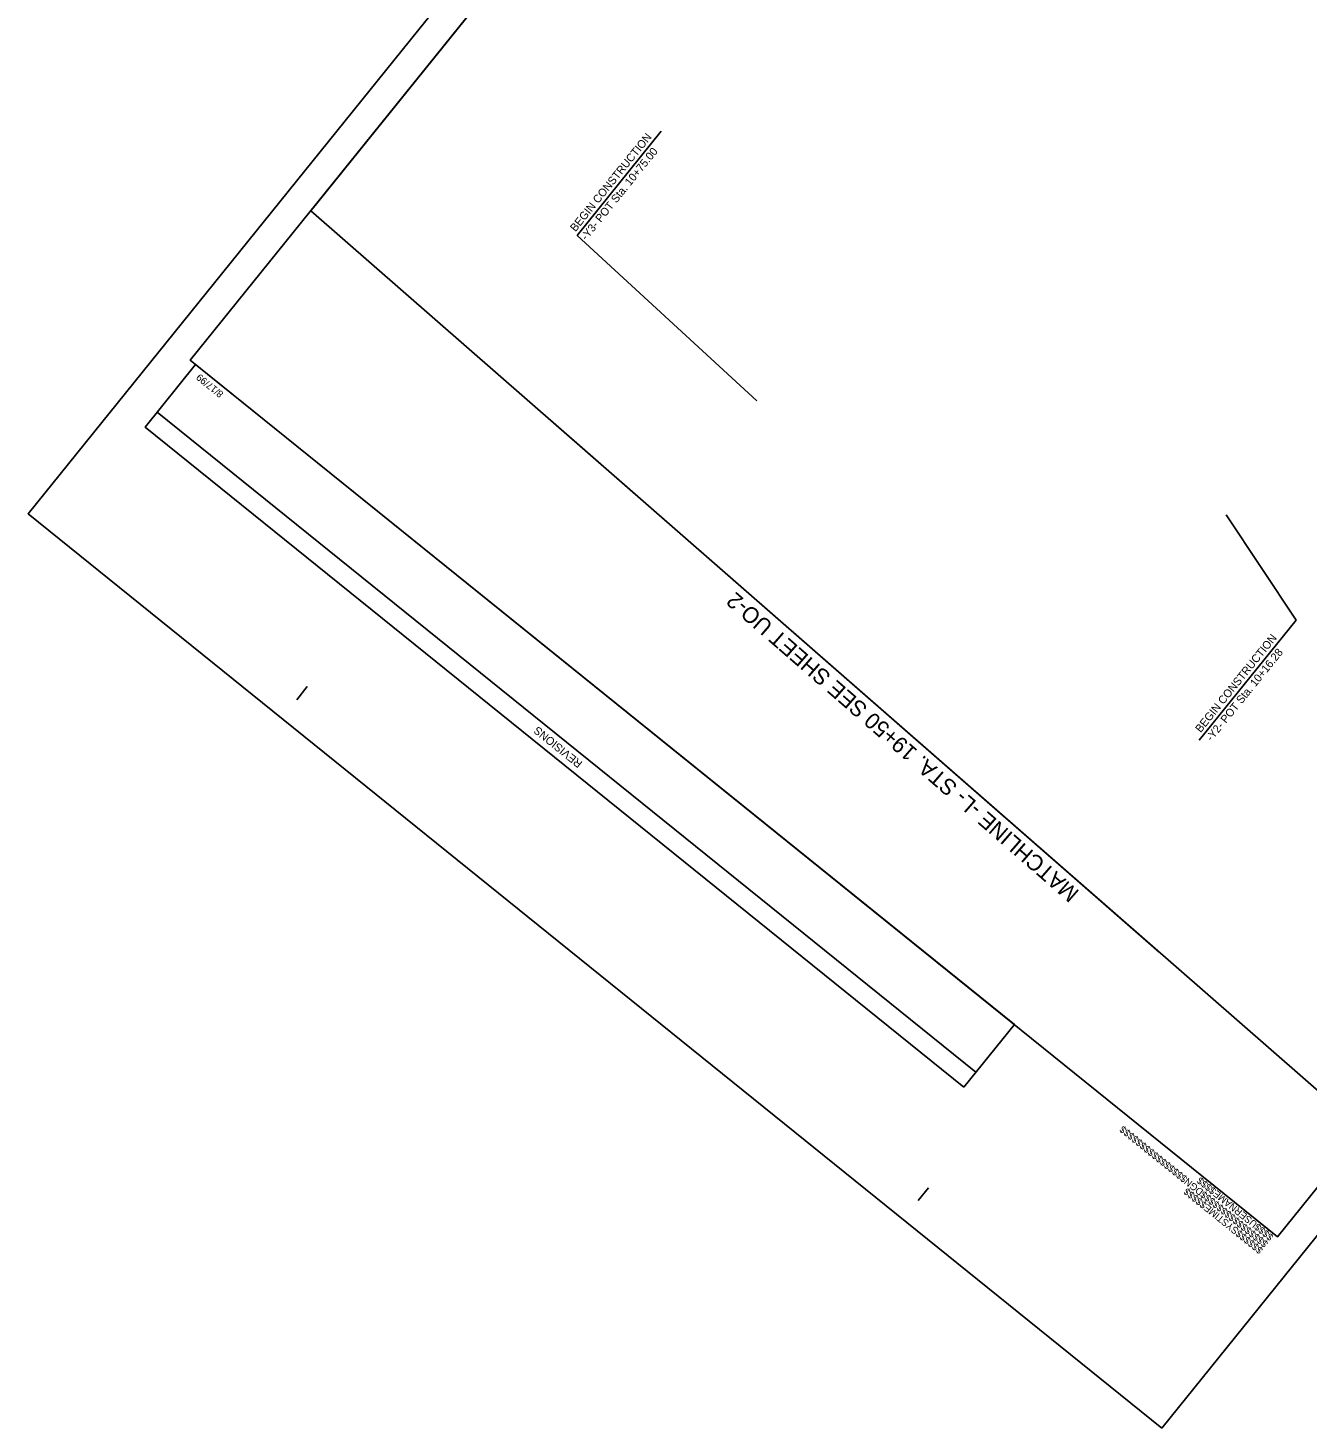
# Model space of a CAD drawing. Extents: x 1487875 to 1489967, y 498345 to 500495.
# Drawn here: x 1487875 to 1488837, y 498345 to 499398 of the extents above; entities that cross this region are included whole.
import ezdxf

# ---------------------------------------------------------------- set-up
doc = ezdxf.new("R2010")
doc.units = 0
for name, color, linetype in [('Exist Utilities Sanitary Sewer Manhole CELL', 7, 'Continuous'), ('Exist Utilities Telephone UG FO SUE LOS C', 7, 'Continuous'), ('Exist Utilities TV UG Cable SUE LOS C', 7, 'Continuous'), ('Exist Utilities Water Fire Hydrant CELL', 7, 'Continuous'), ('Exist Utilities Water UG Line SUE LOS B', 7, 'Continuous'), ('Exist Utilities Water Valve CELL', 7, 'Continuous'), ('Prop UG Pow Cables', 7, 'Continuous')]:
    doc.layers.add(name, color=color, linetype=linetype)

msp = doc.modelspace()

# ---------------------------------------------------------------- linework, layer by layer
at = {"layer": 'Exist Utilities Sanitary Sewer Manhole CELL'}
for p, q in [((1488288, 499241.8), (1488351.3, 499320.3)), ((1488423.2, 499117.7), (1488288, 499241.8)), ((1488775.9, 499031.9), (1488828.6, 498952.8)), ((1488755.7, 498862.4), (1488828.6, 498952.8))]:
    msp.add_line(p, q, dxfattribs=at)
at = {"layer": 'Exist Utilities Telephone UG FO SUE LOS C'}
msp.add_line((1488587.8, 498612.8), (1487972.3, 499109.2), dxfattribs=at)
msp.add_lwpolyline([(1488578.7, 498601.5), (1487963.2, 499097.8), (1488001.2, 499145), (1488616.7, 498648.6)], close=True, dxfattribs=at)
at = {"layer": 'Exist Utilities TV UG Cable SUE LOS C'}
for p, q in [((1487997.2, 499148.2), (1487997.2, 499148.2)), ((1488077.2, 498892.9), (1488085, 498902.7)), ((1488544.3, 498516.3), (1488552.1, 498526)), ((1488814.5, 498489), (1488814.5, 498489))]:
    msp.add_line(p, q, dxfattribs=at)
for points in [[(1488938.9, 500315.8), (1487997.2, 499148.2), (1488814.5, 498489), (1489756.2, 499656.7)], [(1488814.5, 498489), (1487997.2, 499148.1), (1488813.3, 500160.1), (1488842.5, 500136.5), (1488968.1, 500292.2), (1489756.2, 499656.7)]]:
    msp.add_lwpolyline(points, close=True, dxfattribs=at)
at = {"layer": 'Exist Utilities Water Fire Hydrant CELL'}
msp.add_lwpolyline([(1488842.5, 500136.5), (1488813.3, 500160.1), (1488087.8, 499260.5), (1488879.1, 498569.1), (1489756.2, 499656.7), (1488968.1, 500292.2)], close=True, dxfattribs=at)
msp.add_lwpolyline([(1488842.5, 500136.5), (1488813.3, 500160.1), (1488087.8, 499260.5), (1488879.1, 498569.1), (1489756.2, 499656.7), (1488968.1, 500292.2)], close=True, dxfattribs=at)
at = {"layer": 'Exist Utilities Water UG Line SUE LOS B'}
msp.add_line((1488725.6, 498703.2), (1488268.1, 499103), dxfattribs=at)
at = {"layer": 'Prop UG Pow Cables'}
msp.add_lwpolyline([(1488727.6, 498345.3), (1489784.4, 499655.8), (1488932, 500343.2), (1487875.2, 499032.7)], close=True, dxfattribs=at)

# ---------------------------------------------------------------- texts
at = {"layer": 'Exist Utilities Sanitary Sewer Manhole CELL'}
for s, p in [('BEGIN CONSTRUCTION', (1488286.8, 499244.3)), ('-Y3- POT Sta. 10+75.00', (1488294.9, 499237.8)), ('BEGIN CONSTRUCTION', (1488756.8, 498867.7)), ('-Y2- POT Sta. 10+16.28', (1488764.9, 498861.2))]:
    msp.add_text(s, height=6, rotation=51.1156, dxfattribs=at).set_placement(p)
at = {"layer": 'Exist Utilities Telephone UG FO SUE LOS C'}
msp.add_text('REVISIONS', height=6, rotation=141.1156, dxfattribs=at).set_placement((1488292.5, 498845.8))
at = {"layer": 'Exist Utilities TV UG Cable SUE LOS C'}
for s, p in [('8/17/99', (1488022.6, 499123.6)), ('$$$$$$$$$$$$$$$$DGN$$$$$$$$$$$$$$$$', (1488807.9, 498484.6)), ('$$$$USERNAME$$$$', (1488812, 498489.7)), ('$$$$$$SYSTIME$$$$$', (1488804.1, 498479.8))]:
    msp.add_text(s, height=5.25, rotation=141.1157, dxfattribs=at).set_placement(p)
at = {"layer": 'Exist Utilities Water Valve CELL'}
msp.add_text('MATCHLINE -L- STA. 19+50 SEE SHEET UO-2', height=12, rotation=138.9276, dxfattribs=at).set_placement((1488666.2, 498748.7))

doc.saveas('drawing.dxf')
